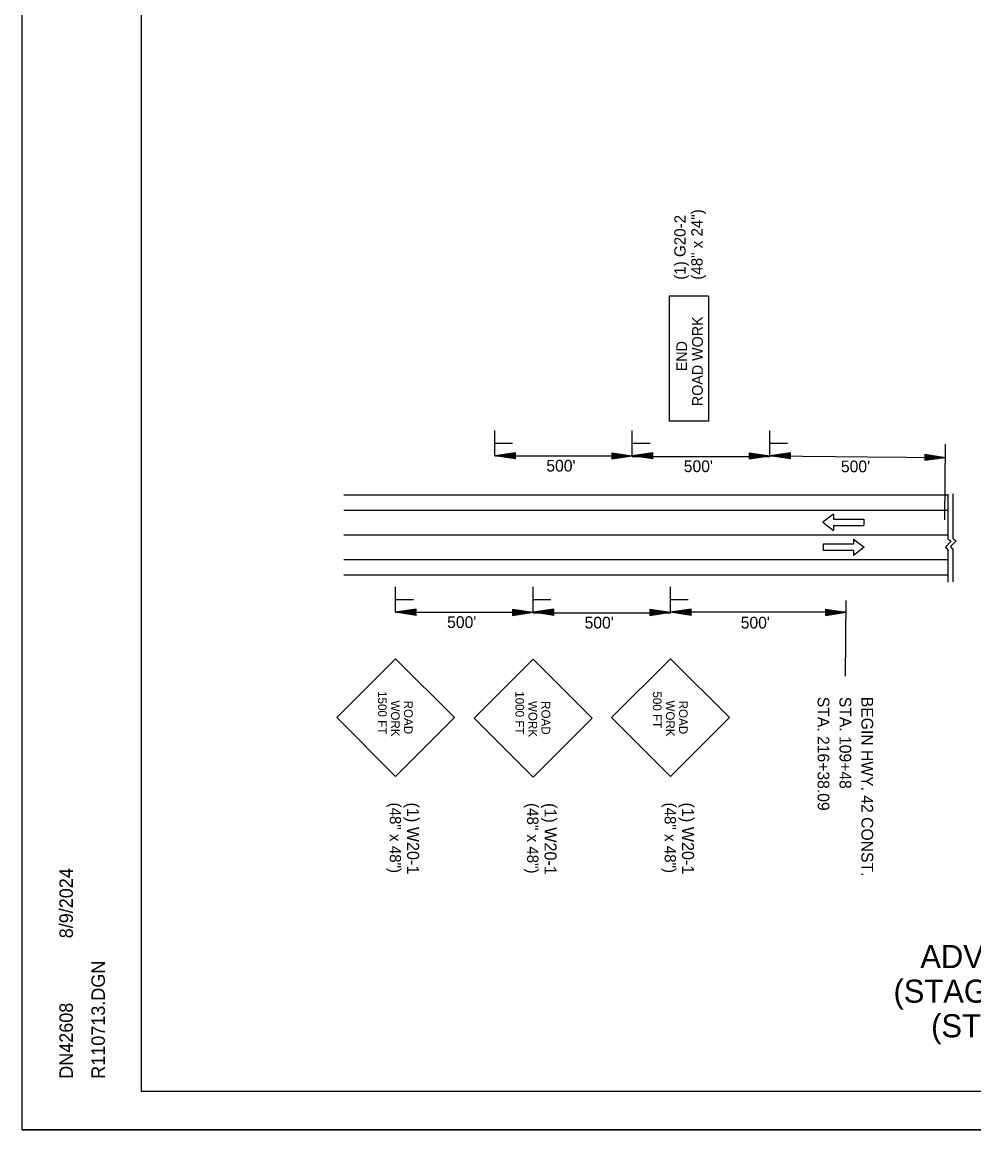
# Model space of a CAD drawing. Extents: x 1678017 to 1687792, y 404433 to 413488.
# Drawn here: x 1679754 to 1680249, y 410689 to 411265 of the extents above; entities that cross this region are included whole.
import ezdxf

# ---------------------------------------------------------------- set-up
doc = ezdxf.new("R2010")
doc.units = 0
for name, color, linetype in [('Default', 7, 'Continuous'), ('S_BUILDING', 7, 'Continuous'), ('S_GRAVEL_ROAD', 7, 'Continuous'), ('S_MSC_PT_SYM', 7, 'Continuous'), ('S_STREAM', 7, 'Continuous'), ('S_TELEPHONE_UTILITIES', 7, 'Continuous')]:
    doc.layers.add(name, color=color, linetype=linetype)

msp = doc.modelspace()

# ---------------------------------------------------------------- linework, layer by layer
at = {"layer": 'Default'}
for p, q in [((1680233.61, 411006.53), (1680233.94, 411045.82)), ((1679999.77, 411039.75), (1680071.2, 411039.75)), ((1680071.2, 411039.49), (1680142.63, 411039.49)), ((1680142.63, 411039.75), (1680193.69, 411039.32)), ((1680193.69, 411039.32), (1680233.88, 411038.98)), ((1680235.3, 410996.4), (1680235.3, 411019.84)), ((1680237.88, 410996.59), (1680237.88, 411020.03)), ((1679921.3, 411011.56), (1680235.3, 411011.56)), ((1680175.78, 411009.5), (1680170.22, 411005.22)), ((1680175.78, 411009.5), (1680175.78, 411006.82)), ((1680170.22, 411005.22), (1680175.78, 411000.93)), ((1680175.78, 411006.82), (1680191.55, 411006.82)), ((1680175.78, 411003.61), (1680191.55, 411003.61)), ((1680175.78, 411003.61), (1680175.78, 411000.93)), ((1680191.55, 411006.82), (1680191.55, 411003.61)), ((1679921.3, 410998.7), (1680235.3, 410998.7)), ((1680186.15, 410996.53), (1680186.15, 410993.85)), ((1680186.15, 410996.53), (1680191.71, 410992.25)), ((1680186.15, 410993.85), (1680170.38, 410993.85)), ((1680170.38, 410993.85), (1680170.38, 410990.64)), ((1680186.15, 410990.64), (1680170.38, 410990.64)), ((1680191.71, 410992.25), (1680186.15, 410987.96)), ((1680186.15, 410990.64), (1680186.15, 410987.96)), ((1680235.3, 410974.18), (1680235.3, 410990.53)), ((1680237.88, 410974.36), (1680237.88, 410990.71)), ((1679921.3, 410985.85), (1680235.3, 410985.85)), ((1680182.06, 410925.24), (1680182.39, 410964.53)), ((1679948.22, 410958.46), (1680019.65, 410958.46)), ((1680019.65, 410958.19), (1680091.08, 410958.19)), ((1680182.34, 410958.46), (1680091.08, 410958.46))]:
    msp.add_line(p, q, dxfattribs=at)
for points in [[(1680235.3, 410996.4), (1680236.95, 410995.42), (1680234, 410992.37), (1680235.3, 410990.53)], [(1680237.88, 410996.59), (1680239.53, 410995.6), (1680236.58, 410992.56), (1680237.88, 410990.71)]]:
    msp.add_lwpolyline(points, dxfattribs=at)
at = {"layer": 'S_BUILDING'}
for p, q in [((1679816.17, 410709.37), (1679816.17, 411736.67)), ((1679816.17, 410709.37), (1679816.17, 410709.37)), ((1681397.07, 410709.37), (1679816.17, 410709.37))]:
    msp.add_line(p, q, dxfattribs=at)
at = {"layer": 'S_GRAVEL_ROAD'}
for p, q in [((1680090.28, 411122.8), (1680090.28, 411057.7)), ((1680110.73, 411122.8), (1680090.28, 411122.8)), ((1680110.73, 411122.8), (1680110.73, 411057.7)), ((1680110.73, 411057.7), (1680090.28, 411057.7)), ((1679999.77, 411039.75), (1679999.77, 411052.99)), ((1680071.2, 411039.75), (1680071.2, 411052.99)), ((1680142.63, 411039.75), (1680142.63, 411052.99)), ((1679999.96, 411046.34), (1680009, 411046.34)), ((1680071.39, 411046.34), (1680080.43, 411046.34)), ((1680142.82, 411046.34), (1680151.86, 411046.34)), ((1679948.22, 410958.46), (1679948.22, 410971.7)), ((1680019.65, 410958.46), (1680019.65, 410971.7)), ((1680091.08, 410958.46), (1680091.08, 410971.7)), ((1679948.42, 410965.05), (1679957.45, 410965.05)), ((1680019.85, 410965.05), (1680028.88, 410965.05)), ((1680091.27, 410965.05), (1680100.31, 410965.05)), ((1679917.59, 410903.69), (1679948.22, 410934.34)), ((1679978.88, 410903.69), (1679948.22, 410934.34)), ((1679989.03, 410903.42), (1680019.65, 410934.07)), ((1680050.3, 410903.42), (1680019.65, 410934.07)), ((1680060.45, 410903.69), (1680091.08, 410934.34)), ((1680121.73, 410903.69), (1680091.08, 410934.34)), ((1679948.22, 410873.04), (1679917.59, 410903.69)), ((1679948.22, 410873.04), (1679978.88, 410903.69)), ((1680019.65, 410872.78), (1679989.03, 410903.42)), ((1680019.65, 410872.78), (1680050.3, 410903.42)), ((1680091.08, 410873.04), (1680060.45, 410903.69)), ((1680091.08, 410873.04), (1680121.73, 410903.69))]:
    msp.add_line(p, q, dxfattribs=at)
at = {"layer": 'S_MSC_PT_SYM'}
for p, q in [((1680010.49, 411041.36), (1679999.77, 411039.75)), ((1680010.49, 411038.15), (1679999.77, 411039.75)), ((1680010.49, 411041.09), (1680001.56, 411039.75)), ((1680010.49, 411038.42), (1680001.56, 411039.75)), ((1680010.49, 411040.82), (1680003.4, 411039.75)), ((1680010.49, 411038.69), (1680003.4, 411039.75)), ((1680010.49, 411040.55), (1680005.19, 411039.75)), ((1680010.49, 411038.96), (1680005.19, 411039.75)), ((1680010.49, 411040.28), (1680007, 411039.75)), ((1680010.49, 411039.23), (1680007, 411039.75)), ((1680010.49, 411040.01), (1680008.79, 411039.75)), ((1680010.49, 411039.5), (1680008.79, 411039.75)), ((1680010.49, 411038.15), (1680010.49, 411041.36)), ((1680060.49, 411041.36), (1680071.2, 411039.75)), ((1680060.49, 411041.36), (1680060.49, 411038.15)), ((1680060.49, 411041.09), (1680069.41, 411039.75)), ((1680060.49, 411040.82), (1680067.57, 411039.75)), ((1680060.49, 411040.55), (1680065.78, 411039.75)), ((1680060.49, 411040.27), (1680063.97, 411039.75)), ((1680060.49, 411040.01), (1680062.18, 411039.75)), ((1680060.49, 411038.15), (1680071.2, 411039.75)), ((1680060.49, 411039.23), (1680063.97, 411039.75)), ((1680060.49, 411038.69), (1680067.57, 411039.75)), ((1680060.49, 411038.42), (1680069.41, 411039.75)), ((1680060.49, 411038.96), (1680065.78, 411039.75)), ((1680060.49, 411039.5), (1680062.18, 411039.75)), ((1680081.91, 411041.36), (1680071.2, 411039.75)), ((1680081.91, 411038.15), (1680071.2, 411039.75)), ((1680081.91, 411041.09), (1680072.99, 411039.75)), ((1680081.91, 411038.42), (1680072.99, 411039.75)), ((1680081.91, 411040.82), (1680074.83, 411039.75)), ((1680081.91, 411038.69), (1680074.83, 411039.75)), ((1680081.91, 411040.55), (1680076.62, 411039.75)), ((1680081.91, 411038.96), (1680076.62, 411039.75)), ((1680081.91, 411040.28), (1680078.43, 411039.75)), ((1680081.91, 411039.23), (1680078.43, 411039.75)), ((1680081.91, 411040.01), (1680080.22, 411039.75)), ((1680081.91, 411039.5), (1680080.22, 411039.75)), ((1680081.91, 411038.15), (1680081.91, 411041.36)), ((1680131.91, 411041.36), (1680142.63, 411039.75)), ((1680131.91, 411041.36), (1680131.91, 411038.15)), ((1680131.91, 411041.09), (1680140.84, 411039.75)), ((1680131.91, 411040.82), (1680139, 411039.75)), ((1680131.91, 411040.55), (1680137.21, 411039.75)), ((1680131.91, 411040.27), (1680135.4, 411039.75)), ((1680131.91, 411040.01), (1680133.61, 411039.75)), ((1680131.91, 411038.15), (1680142.63, 411039.75)), ((1680131.91, 411039.23), (1680135.4, 411039.75)), ((1680131.91, 411038.69), (1680139, 411039.75)), ((1680131.91, 411038.42), (1680140.84, 411039.75)), ((1680131.91, 411038.96), (1680137.21, 411039.75)), ((1680131.91, 411039.5), (1680133.61, 411039.75)), ((1680153.34, 411041.36), (1680142.63, 411039.75)), ((1680153.34, 411038.15), (1680142.63, 411039.75)), ((1680153.34, 411041.09), (1680144.42, 411039.75)), ((1680153.34, 411038.42), (1680144.42, 411039.75)), ((1680153.34, 411040.82), (1680146.26, 411039.75)), ((1680153.34, 411038.69), (1680146.26, 411039.75)), ((1680153.34, 411040.55), (1680148.04, 411039.75)), ((1680153.34, 411038.96), (1680148.04, 411039.75)), ((1680153.34, 411040.28), (1680149.86, 411039.75)), ((1680153.34, 411039.23), (1680149.86, 411039.75)), ((1680153.34, 411040.01), (1680151.65, 411039.75)), ((1680153.34, 411039.5), (1680151.65, 411039.75)), ((1680153.34, 411038.15), (1680153.34, 411041.36)), ((1680223.18, 411040.68), (1680223.15, 411037.46)), ((1680223.15, 411037.46), (1680233.88, 411038.98)), ((1680223.16, 411038.54), (1680226.65, 411039.04)), ((1680223.16, 411038.27), (1680228.47, 411039.02)), ((1680223.16, 411038), (1680230.25, 411039.01)), ((1680223.16, 411037.73), (1680232.09, 411038.99)), ((1680223.17, 411039.87), (1680228.47, 411039.02)), ((1680223.17, 411039.59), (1680226.65, 411039.04)), ((1680223.17, 411039.32), (1680224.86, 411039.05)), ((1680223.17, 411038.82), (1680224.86, 411039.05)), ((1680223.18, 411040.68), (1680233.88, 411038.98)), ((1680223.18, 411040.41), (1680232.09, 411038.99)), ((1680223.18, 411040.14), (1680230.25, 411039.01)), ((1679958.94, 410960.07), (1679948.22, 410958.46)), ((1679958.94, 410956.86), (1679948.22, 410958.46)), ((1679958.94, 410959.8), (1679950.01, 410958.46)), ((1679958.94, 410957.12), (1679950.01, 410958.46)), ((1679958.94, 410959.53), (1679951.86, 410958.46)), ((1679958.94, 410957.4), (1679951.86, 410958.46)), ((1679958.94, 410959.26), (1679953.64, 410958.46)), ((1679958.94, 410957.66), (1679953.64, 410958.46)), ((1679958.94, 410958.99), (1679955.46, 410958.46)), ((1679958.94, 410957.94), (1679955.46, 410958.46)), ((1679958.94, 410958.71), (1679957.25, 410958.46)), ((1679958.94, 410958.21), (1679957.25, 410958.46)), ((1679958.94, 410956.86), (1679958.94, 410960.07)), ((1680008.94, 410960.07), (1680019.65, 410958.46)), ((1680008.94, 410960.07), (1680008.94, 410956.86)), ((1680008.94, 410959.8), (1680017.86, 410958.46)), ((1680008.94, 410959.53), (1680016.02, 410958.46)), ((1680008.94, 410959.26), (1680014.24, 410958.46)), ((1680008.94, 410958.98), (1680012.42, 410958.46)), ((1680008.94, 410958.71), (1680010.63, 410958.46)), ((1680008.94, 410956.86), (1680019.65, 410958.46)), ((1680008.94, 410957.94), (1680012.42, 410958.46)), ((1680008.94, 410957.4), (1680016.02, 410958.46)), ((1680008.94, 410957.12), (1680017.86, 410958.46)), ((1680008.94, 410957.66), (1680014.24, 410958.46)), ((1680008.94, 410958.21), (1680010.63, 410958.46)), ((1680030.37, 410960.07), (1680019.65, 410958.46)), ((1680030.37, 410956.86), (1680019.65, 410958.46)), ((1680030.37, 410959.8), (1680021.44, 410958.46)), ((1680030.37, 410957.12), (1680021.44, 410958.46)), ((1680030.37, 410959.53), (1680023.28, 410958.46)), ((1680030.37, 410957.4), (1680023.28, 410958.46)), ((1680030.37, 410959.26), (1680025.07, 410958.46)), ((1680030.37, 410957.66), (1680025.07, 410958.46)), ((1680030.37, 410958.99), (1680026.88, 410958.46)), ((1680030.37, 410957.94), (1680026.88, 410958.46)), ((1680030.37, 410958.71), (1680028.67, 410958.46)), ((1680030.37, 410958.21), (1680028.67, 410958.46)), ((1680030.37, 410956.86), (1680030.37, 410960.07)), ((1680080.37, 410960.07), (1680091.08, 410958.46)), ((1680080.37, 410960.07), (1680080.37, 410956.86)), ((1680080.37, 410959.8), (1680089.29, 410958.46)), ((1680080.37, 410959.53), (1680087.45, 410958.46)), ((1680080.37, 410959.26), (1680085.67, 410958.46)), ((1680080.37, 410958.98), (1680083.85, 410958.46)), ((1680080.37, 410958.71), (1680082.06, 410958.46)), ((1680080.37, 410956.86), (1680091.08, 410958.46)), ((1680080.37, 410957.94), (1680083.85, 410958.46)), ((1680080.37, 410957.4), (1680087.45, 410958.46)), ((1680080.37, 410957.12), (1680089.29, 410958.46)), ((1680080.37, 410957.66), (1680085.67, 410958.46)), ((1680080.37, 410958.21), (1680082.06, 410958.46)), ((1680101.8, 410960.07), (1680091.08, 410958.46)), ((1680101.8, 410956.86), (1680091.08, 410958.46)), ((1680101.8, 410959.8), (1680092.87, 410958.46)), ((1680101.8, 410957.12), (1680092.87, 410958.46)), ((1680101.8, 410959.53), (1680094.71, 410958.46)), ((1680101.8, 410957.4), (1680094.71, 410958.46)), ((1680101.8, 410959.26), (1680096.5, 410958.46)), ((1680101.8, 410957.66), (1680096.5, 410958.46)), ((1680101.8, 410958.99), (1680098.31, 410958.46)), ((1680101.8, 410957.94), (1680098.31, 410958.46)), ((1680101.8, 410958.71), (1680100.1, 410958.46)), ((1680101.8, 410958.21), (1680100.1, 410958.46)), ((1680101.8, 410956.86), (1680101.8, 410960.07)), ((1680171.68, 410960.07), (1680182.39, 410958.46)), ((1680171.68, 410960.07), (1680171.68, 410956.86)), ((1680171.68, 410959.8), (1680180.6, 410958.46)), ((1680171.68, 410959.53), (1680178.76, 410958.46)), ((1680171.68, 410959.26), (1680176.98, 410958.46)), ((1680171.68, 410958.98), (1680175.16, 410958.46)), ((1680171.68, 410958.71), (1680173.37, 410958.46)), ((1680171.68, 410956.86), (1680182.39, 410958.46)), ((1680171.68, 410957.94), (1680175.16, 410958.46)), ((1680171.68, 410957.4), (1680178.76, 410958.46)), ((1680171.68, 410957.12), (1680180.6, 410958.46)), ((1680171.68, 410957.66), (1680176.98, 410958.46)), ((1680171.68, 410958.21), (1680173.37, 410958.46))]:
    msp.add_line(p, q, dxfattribs=at)
at = {"layer": 'S_STREAM'}
for p, q in [((1680101.8, 410960.07), (1680091.08, 410958.46)), ((1680101.8, 410956.86), (1680091.08, 410958.46)), ((1680101.8, 410959.8), (1680092.87, 410958.46)), ((1680101.8, 410957.12), (1680092.87, 410958.46)), ((1680101.8, 410959.53), (1680094.71, 410958.46)), ((1680101.8, 410957.4), (1680094.71, 410958.46)), ((1680101.8, 410959.26), (1680096.5, 410958.46)), ((1680101.8, 410957.66), (1680096.5, 410958.46)), ((1680101.8, 410958.99), (1680098.31, 410958.46)), ((1680101.8, 410957.94), (1680098.31, 410958.46)), ((1680101.8, 410958.71), (1680100.1, 410958.46)), ((1680101.8, 410958.21), (1680100.1, 410958.46)), ((1680101.8, 410956.86), (1680101.8, 410960.07)), ((1679754.17, 410689.48), (1681420.84, 410689.48))]:
    msp.add_line(p, q, dxfattribs=at)
for points in [[(1679754.14, 411756.14), (1681420.84, 411756.14), (1681420.84, 410689.45), (1679754.14, 410689.45)], [(1680985.77, 411736.67), (1681083.87, 411736.67), (1681083.87, 411687.27), (1681164.43, 411687.27), (1681280.43, 411687.27), (1681280.43, 411565.61), (1681397.07, 411565.61), (1681397.07, 410709.37), (1679816.17, 410709.37), (1679816.17, 411736.67)]]:
    msp.add_lwpolyline(points, close=True, dxfattribs=at)
at = {"layer": 'S_TELEPHONE_UTILITIES'}
for p, q in [((1679921.3, 411019.56), (1680235.3, 411019.56)), ((1679921.3, 410977.85), (1680235.3, 410977.85))]:
    msp.add_line(p, q, dxfattribs=at)

# ---------------------------------------------------------------- texts
at = {"layer": 'Default'}
for p in [(1680026.53, 411031.58), (1680097.95, 411031.32), (1680179.61, 411031.23)]:
    msp.add_text("500'", height=6.1, dxfattribs=at).set_placement(p)
for s, rotation, p in [("500'", 360, (1679974.98, 410950.29)), ("500'", 360, (1680046.41, 410950.02)), ("500'", 360, (1680127.54, 410950.02)), ('STA. 216+38.09', 270, (1680167.51, 410914.53)), ('STA. 109+48', 270, (1680178.89, 410914.53)), ('BEGIN HWY. 42 CONST.', 270, (1680190.27, 410914.53))]:
    msp.add_text(s, height=6.1, rotation=rotation, dxfattribs=at).set_placement(p)
at = {"layer": 'S_BUILDING'}
for s, p in [('8/9/2024', (1679780.5, 410789.01)), ('R110713.DGN', (1679797.13, 410715.99)), ('DN42608', (1679780.5, 410715.99))]:
    msp.add_text(s, height=7, rotation=90, dxfattribs=at).set_placement(p)
at = {"layer": 'S_GRAVEL_ROAD'}
for s, height, rotation, p in [('(1) G20-2', 5.881, 90, (1680098.92, 411131.3)), ('(48" x 24")', 5.88, 90, (1680107.73, 411131.3)), ('ROAD WORK', 5.557, 90, (1680107.84, 411065.58)), ('END', 5.557, 90, (1680099.64, 411083.72)), ('1500 FT', 4.516, 270.00057, (1679939.04, 410917.5)), ('1000 FT', 4.516, 270.00057, (1680010.47, 410917.42)), (' 500 FT', 4.516, 270.00057, (1680081.9, 410919.01)), ('WORK', 4.515, 270.00004, (1679945.82, 410912.63)), ('ROAD', 4.516, 270.00045, (1679952.59, 410912.54)), ('WORK', 4.515, 270.00004, (1680017.25, 410912.37)), ('ROAD', 4.516, 270.00045, (1680024.02, 410912.28)), ('WORK', 4.515, 270.00004, (1680088.68, 410912.63)), ('ROAD', 4.516, 270.00045, (1680095.45, 410912.54)), ('(48" x 48")', 5.88, 270, (1679945.13, 410859.55)), ('(1) W20-1', 6.273, 270, (1679954.16, 410859.55)), ('(48" x 48")', 5.88, 270, (1680016.56, 410859.29)), ('(1) W20-1', 6.273, 270, (1680025.58, 410859.29)), ('(48" x 48")', 5.88, 270, (1680087.99, 410859.55)), ('(1) W20-1', 6.273, 270, (1680097.01, 410859.55))]:
    msp.add_text(s, height=height, rotation=rotation, dxfattribs=at).set_placement(p)
at = {"layer": 'S_MSC_PT_SYM'}
for s, p in [('ADVANCE WARNING ', (1680220.89, 410773.55)), ('(STAGE 1 SITES 1 & 2)', (1680206.95, 410755.55)), ('(STAGE 2 SITE 1)', (1680226.51, 410737.55))]:
    msp.add_text(s, height=12, rotation=360, dxfattribs=at).set_placement(p)

doc.saveas('drawing.dxf')
